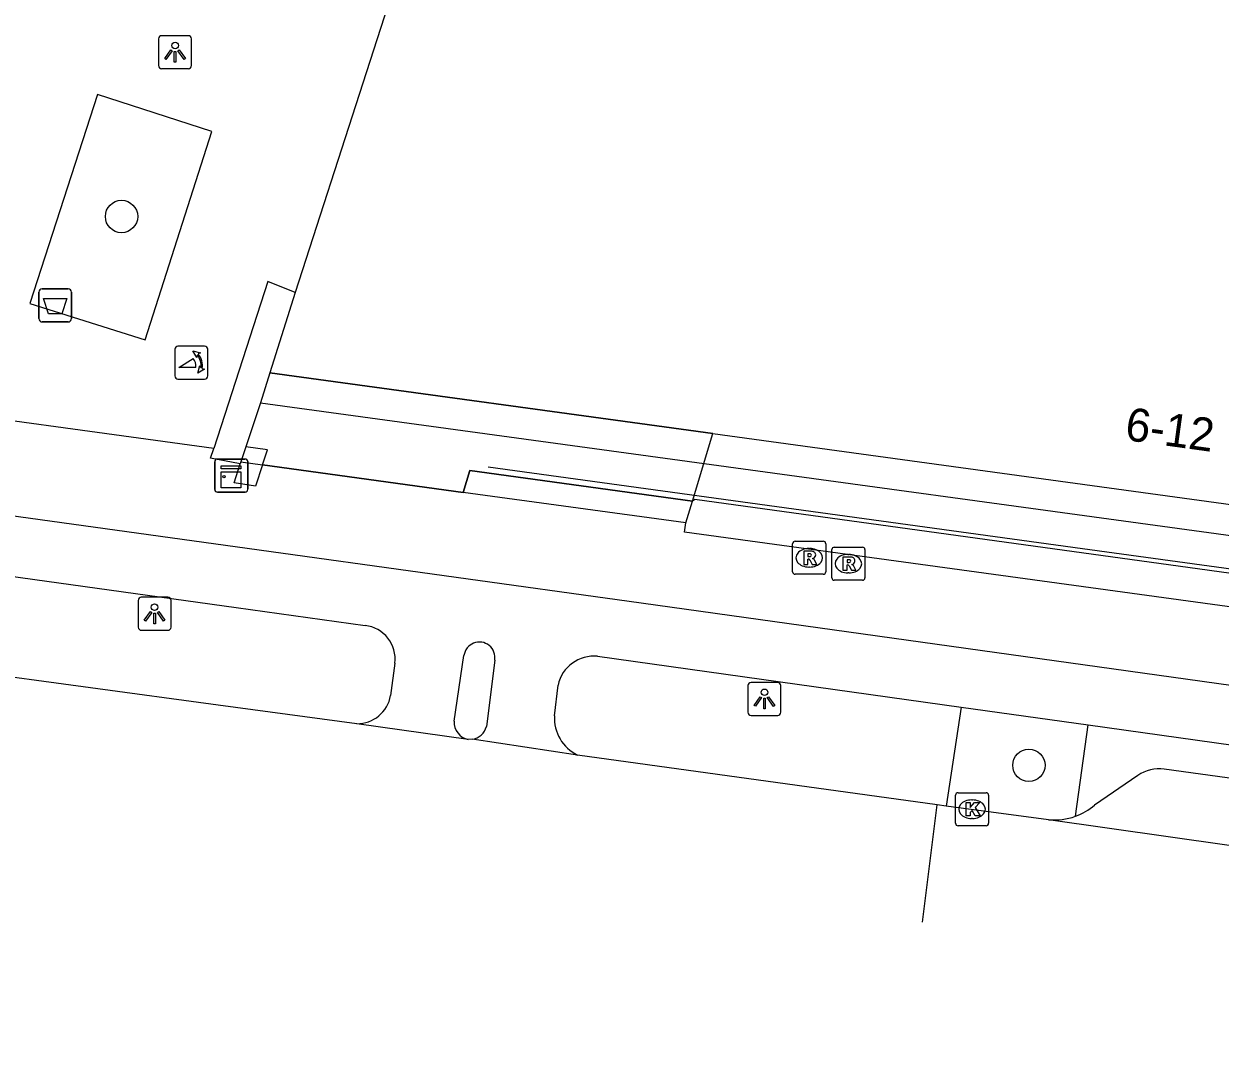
# Model space of a CAD drawing. Extents: x 160676 to 161153, y 383244 to 383713.
# Drawn here: x 160899.21 to 160935.37, y 383255.03 to 383286.17 of the extents above; entities that cross this region are included whole.
import ezdxf

# ---------------------------------------------------------------- set-up
doc = ezdxf.new("R2010")
doc.units = 0
for name, color, linetype in [('IMGEO_Afvalbak', 7, 'Continuous'), ('IMGEO_Berm_open', 7, 'Continuous'), ('IMGEO_Boom', 7, 'Continuous'), ('IMGEO_Fietspad_gesloten', 7, 'Continuous'), ('IMGEO_Kast', 7, 'Continuous'), ('IMGEO_Kolk', 7, 'Continuous'), ('IMGEO_Lichtpunt', 7, 'Continuous'), ('IMGEO_Lijnafwatering', 7, 'Continuous'), ('IMGEO_Pand', 7, 'Continuous'), ('IMGEO_Pand_nummerreeks', 7, 'Continuous'), ('IMGEO_Pand_overbouw', 7, 'Continuous'), ('IMGEO_Parkeervlak_open', 7, 'Continuous'), ('IMGEO_Poller', 7, 'Continuous'), ('IMGEO_Rijbaan_lokaal_gesloten', 7, 'Continuous'), ('IMGEO_Rioolput', 7, 'Continuous'), ('IMGEO_Voetpad_open', 7, 'Continuous')]:
    doc.layers.add(name, color=color, linetype=linetype)

msp = doc.modelspace()

# ---------------------------------------------------------------- linework, layer by layer
at = {"layer": 'IMGEO_Afvalbak'}
for p, q in [((160899.762, 383278.159), (160900.552, 383278.159)), ((160900.552, 383278.159), (160899.762, 383278.159)), ((160899.662, 383277.259), (160899.662, 383278.059)), ((160899.662, 383278.059), (160899.662, 383277.259)), ((160900.652, 383278.059), (160900.652, 383277.259)), ((160900.652, 383277.259), (160900.652, 383278.059)), ((160900.552, 383277.159), (160899.762, 383277.159)), ((160899.762, 383277.159), (160900.552, 383277.159))]:
    msp.add_line(p, q, dxfattribs=at)
msp.add_lwpolyline([(160899.805, 383277.873), (160900.509, 383277.873), (160900.36, 383277.403), (160899.954, 383277.403), (160899.805, 383277.873)], dxfattribs=at)
for centre, start, end in [((160899.762, 383278.059), 90, 180), ((160899.762, 383278.059), 90, 180), ((160900.552, 383278.059), 0, 90), ((160900.552, 383278.059), 360, 90), ((160899.762, 383277.259), 180, 270), ((160899.762, 383277.259), 180, 270), ((160900.552, 383277.259), 270, 0), ((160900.552, 383277.259), 270, 0)]:
    msp.add_arc(centre, 0.1, start, end, dxfattribs=at)
at = {"layer": 'IMGEO_Berm_open'}
for points in [[(160927.544, 383265.517), (160927.098, 383262.525)], [(160931.002, 383262.219), (160931.387, 383264.979)]]:
    msp.add_lwpolyline(points, dxfattribs=at)
at = {"layer": 'IMGEO_Boom'}
for centre in [(160902.164, 383280.346), (160929.593, 383263.759)]:
    msp.add_circle(centre, 0.489, dxfattribs=at)
at = {"layer": 'IMGEO_Fietspad_gesloten'}
for points in [[(160794.456, 383285.635), (160802.2, 383284.6), (160821.26, 383282.051), (160905.957, 383270.323), (160917.876, 383268.672), (161015.584, 383255.032)], [(160879.175, 383272.209), (160905.628, 383268.525), (160909.53, 383267.981)], [(160912.222, 383265.092), (160912.515, 383267.079)], [(160913.448, 383266.937), (160913.196, 383264.937)], [(160916.557, 383267.054), (160927.544, 383265.517)], [(160910.426, 383266.846), (160910.299, 383265.865)], [(160915.249, 383265.258), (160915.362, 383266.182)], [(160927.544, 383265.517), (160931.387, 383264.979)], [(160931.387, 383264.979), (160946.189, 383262.908)]]:
    msp.add_lwpolyline(points, dxfattribs=at)
for centre, radius, start, end in [((160909.423, 383266.976), 1.011, 352.6266, 83.9504), ((160912.982, 383267.013), 0.472, 350.6807, 172.0116), ((160916.446, 383265.952), 1.108, 84.2265, 168.0105), ((160909.282, 383266.048), 1.033, 269.5346, 349.8011), ((160916.495, 383265.191), 1.247, 176.9091, 243.9629), ((160912.736, 383265.049), 0.516, 175.2135, 259.3881), ((160912.689, 383265.063), 0.523, 277.8466, 346.0697)]:
    msp.add_arc(centre, radius, start, end, dxfattribs=at)
at = {"layer": 'IMGEO_Kast'}
for p, q in [((160904.98, 383272.092), (160904.98, 383272.933)), ((160904.98, 383272.933), (160904.98, 383272.092)), ((160905.055, 383273.017), (160905.896, 383273.017)), ((160905.896, 383273.017), (160905.055, 383273.017)), ((160905.98, 383272.942), (160905.98, 383272.101)), ((160905.98, 383272.101), (160905.98, 383272.942)), ((160905.905, 383272.017), (160905.064, 383272.017)), ((160905.064, 383272.017), (160905.905, 383272.017))]:
    msp.add_line(p, q, dxfattribs=at)
for points in [[(160905.175, 383272.807), (160905.775, 383272.807), (160905.775, 383272.722), (160905.175, 383272.722), (160905.175, 383272.807)], [(160905.175, 383272.632), (160905.775, 383272.632), (160905.775, 383272.143), (160905.175, 383272.143), (160905.175, 383272.632)]]:
    msp.add_lwpolyline(points, dxfattribs=at)
msp.add_circle((160905.259, 383272.481), 0.0377, dxfattribs=at)
for centre, start, end in [((160905.058, 383272.939), 92.4484, 184.2845), ((160905.058, 383272.939), 92.4484, 184.2845), ((160905.902, 383272.939), 2.4484, 94.2845), ((160905.902, 383272.939), 2.4484, 94.2845), ((160905.058, 383272.095), 182.4484, 274.2845), ((160905.058, 383272.095), 182.4484, 274.2845), ((160905.902, 383272.095), 272.4484, 4.2845), ((160905.902, 383272.095), 272.4484, 4.2845)]:
    msp.add_arc(centre, 0.0779, start, end, dxfattribs=at)
at = {"layer": 'IMGEO_Kolk'}
for p, q in [((160927.451, 383262.932), (160928.303, 383262.932)), ((160927.376, 383262.006), (160927.376, 383262.858)), ((160927.864, 383262.712), (160927.889, 383262.712)), ((160928.377, 383262.858), (160928.377, 383262.006)), ((160928.303, 383261.932), (160927.451, 383261.932)), ((160927.887, 383262.152), (160927.862, 383262.152))]:
    msp.add_line(p, q, dxfattribs=at)
for points in [[(160927.451, 383262.932), (160928.303, 383262.932)], [(160927.376, 383262.006), (160927.376, 383262.858)], [(160927.697, 383262.632), (160927.82, 383262.632), (160927.82, 383262.481), (160927.95, 383262.632), (160928.114, 383262.632), (160927.968, 383262.481), (160928.121, 383262.232), (160927.969, 383262.232), (160927.884, 383262.396), (160927.82, 383262.329), (160927.82, 383262.232), (160927.697, 383262.232), (160927.697, 383262.632)], [(160928.377, 383262.858), (160928.377, 383262.006)], [(160928.303, 383261.932), (160927.451, 383261.932)]]:
    msp.add_lwpolyline(points, dxfattribs=at)
for centre, start, end in [((160927.453, 383262.856), 91.552, 178.448), ((160927.453, 383262.856), 91.552, 178.448), ((160928.301, 383262.856), 1.552, 88.448), ((160928.301, 383262.856), 1.552, 88.448), ((160927.453, 383262.008), 181.552, 268.448), ((160927.453, 383262.008), 181.552, 268.448), ((160928.301, 383262.008), 271.552, 358.448), ((160928.301, 383262.008), 271.552, 358.448)]:
    msp.add_arc(centre, 0.0765, start, end, dxfattribs=at)
for centre, major_axis, ratio, start_param, end_param in [((160927.863, 383262.432), (-0.387, 0.002), 0.722429, 4.712389, 7.853982), ((160927.888, 383262.432), (-0.39, 0.002), 0.717154, 1.570796, 4.712389)]:
    msp.add_ellipse(centre, major_axis=major_axis, ratio=ratio, start_param=start_param, end_param=end_param, dxfattribs=at)
at = {"layer": 'IMGEO_Lichtpunt'}
for p, q in [((160903.283, 383285.716), (160903.283, 383284.909)), ((160903.283, 383285.716), (160903.283, 383284.909)), ((160904.185, 383285.811), (160903.377, 383285.811)), ((160904.185, 383285.811), (160903.377, 383285.811)), ((160904.279, 383284.909), (160904.279, 383285.716)), ((160904.279, 383284.909), (160904.279, 383285.716)), ((160903.377, 383284.815), (160904.185, 383284.815)), ((160903.377, 383284.815), (160904.185, 383284.815)), ((160902.665, 383268.743), (160902.665, 383267.936)), ((160902.665, 383268.743), (160902.665, 383267.936)), ((160903.567, 383268.838), (160902.759, 383268.838)), ((160903.567, 383268.838), (160902.759, 383268.838)), ((160903.661, 383267.936), (160903.661, 383268.743)), ((160903.661, 383267.936), (160903.661, 383268.743)), ((160902.759, 383267.842), (160903.567, 383267.842)), ((160902.759, 383267.842), (160903.567, 383267.842)), ((160922.002, 383266.263), (160921.194, 383266.263)), ((160922.002, 383266.263), (160921.194, 383266.263)), ((160921.1, 383266.168), (160921.1, 383265.361)), ((160921.1, 383266.168), (160921.1, 383265.361)), ((160922.096, 383265.361), (160922.096, 383266.168)), ((160922.096, 383265.361), (160922.096, 383266.168)), ((160921.194, 383265.267), (160922.002, 383265.267)), ((160921.194, 383265.267), (160922.002, 383265.267))]:
    msp.add_line(p, q, dxfattribs=at)
for points in [[(160903.657, 383285.38), (160903.696, 383285.352), (160903.508, 383285.09), (160903.47, 383285.117), (160903.657, 383285.38)], [(160903.869, 383285.352), (160903.907, 383285.379), (160904.094, 383285.117), (160904.055, 383285.089), (160903.869, 383285.352)], [(160903.759, 383285.332), (160903.806, 383285.332), (160903.806, 383285.01), (160903.759, 383285.01), (160903.759, 383285.332)], [(160903.039, 383268.407), (160903.078, 383268.379), (160902.89, 383268.117), (160902.852, 383268.144), (160903.039, 383268.407)], [(160903.141, 383268.359), (160903.188, 383268.359), (160903.188, 383268.037), (160903.141, 383268.037), (160903.141, 383268.359)], [(160903.251, 383268.379), (160903.289, 383268.406), (160903.476, 383268.144), (160903.437, 383268.116), (160903.251, 383268.379)], [(160921.474, 383265.832), (160921.513, 383265.804), (160921.325, 383265.542), (160921.287, 383265.569), (160921.474, 383265.832)], [(160921.686, 383265.804), (160921.724, 383265.831), (160921.911, 383265.569), (160921.872, 383265.541), (160921.686, 383265.804)], [(160921.576, 383265.784), (160921.623, 383265.784), (160921.623, 383265.462), (160921.576, 383265.462), (160921.576, 383265.784)]]:
    msp.add_lwpolyline(points, dxfattribs=at)
for centre in [(160903.782, 383285.514), (160903.164, 383268.541), (160921.599, 383265.966)]:
    msp.add_circle(centre, 0.0994, dxfattribs=at)
for centre, start, end in [((160903.377, 383285.716), 90, 180), ((160903.377, 383285.716), 90, 180), ((160904.185, 383285.716), 0, 90), ((160904.185, 383285.716), 0, 90), ((160903.377, 383284.909), 180, 270), ((160903.377, 383284.909), 180, 270), ((160904.185, 383284.909), 270, 0), ((160904.185, 383284.909), 270, 360), ((160902.759, 383268.743), 90, 180), ((160902.759, 383268.743), 90, 180), ((160903.567, 383268.743), 0, 90), ((160903.567, 383268.743), 0, 90), ((160902.759, 383267.936), 180, 270), ((160902.759, 383267.936), 180, 270), ((160903.567, 383267.936), 270, 0), ((160903.567, 383267.936), 270, 360), ((160921.194, 383266.168), 90, 180), ((160921.194, 383266.168), 90, 180), ((160922.002, 383266.168), 0, 90), ((160922.002, 383266.168), 0, 90), ((160921.194, 383265.361), 180, 270), ((160921.194, 383265.361), 180, 270), ((160922.002, 383265.361), 270, 0), ((160922.002, 383265.361), 270, 360)]:
    msp.add_arc(centre, 0.0946, start, end, dxfattribs=at)
at = {"layer": 'IMGEO_Lijnafwatering'}
for points in [[(160931.212, 383270.307), (160913.243, 383272.77)], [(160949.181, 383267.844), (160931.212, 383270.307)]]:
    msp.add_lwpolyline(points, dxfattribs=at)
at = {"layer": 'IMGEO_Pand'}
for points in [[(160911.5, 383290.712), (160907.414, 383278.054)], [(160907.414, 383278.054), (160906.652, 383275.617)], [(160906.652, 383275.617), (160920.037, 383273.784), (160958.187, 383268.56), (160960.344, 383268.267)], [(160906.425, 383272.844), (160906.572, 383273.293), (160905.926, 383273.383), (160905.772, 383272.934), (160905.752, 383272.875)], [(160906.425, 383272.844), (160906.213, 383272.197), (160905.572, 383272.294), (160905.752, 383272.875)], [(160919.42, 383271.745), (160912.693, 383272.666), (160912.494, 383272.008)], [(160919.221, 383271.087), (160912.494, 383272.008)], [(160919.221, 383271.087), (160919.42, 383271.745)]]:
    msp.add_lwpolyline(points, dxfattribs=at)
at = {"layer": 'IMGEO_Pand_overbouw'}
msp.add_lwpolyline([(160920.037, 383273.784), (160906.652, 383275.617), (160906.361, 383274.718), (160905.926, 383273.383), (160905.772, 383272.934), (160906.425, 383272.844), (160912.494, 383272.008), (160912.693, 383272.666), (160919.42, 383271.745)], close=True, dxfattribs=at)
at = {"layer": 'IMGEO_Parkeervlak_open'}
for points in [[(160946.008, 383261.707), (160945.542, 383262.006), (160933.685, 383263.646)], [(160932.889, 383263.454), (160931.577, 383262.554)]]:
    msp.add_lwpolyline(points, dxfattribs=at)
for centre, radius, start, end in [((160933.559, 383262.422), 1.231, 84.1317, 122.9904), ((160930.366, 383263.979), 1.871, 264.5955, 289.8629), ((160930.363, 383263.977), 1.87, 289.9775, 310.4734)]:
    msp.add_arc(centre, radius, start, end, dxfattribs=at)
at = {"layer": 'IMGEO_Poller'}
for p, q in [((160903.775, 383276.333), (160903.775, 383275.526)), ((160903.775, 383276.333), (160903.775, 383275.526)), ((160904.677, 383276.428), (160903.869, 383276.428)), ((160904.677, 383276.428), (160903.869, 383276.428)), ((160904.771, 383275.526), (160904.771, 383276.333)), ((160904.771, 383275.526), (160904.771, 383276.333)), ((160903.869, 383275.431), (160904.677, 383275.431)), ((160903.869, 383275.431), (160904.677, 383275.431))]:
    msp.add_line(p, q, dxfattribs=at)
for points in [[(160904.41, 383275.784), (160903.897, 383275.784), (160904.327, 383276.059)], [(160904.454, 383276.157), (160904.442, 383276.084), (160904.317, 383276.289)], [(160904.317, 383276.289), (160904.548, 383276.223), (160904.477, 383276.191)], [(160904.47, 383275.612), (160904.536, 383275.843), (160904.566, 383275.775)], [(160904.602, 383275.748), (160904.674, 383275.737), (160904.47, 383275.612)]]:
    msp.add_lwpolyline(points, dxfattribs=at)
for centre, radius, start, end in [((160903.869, 383276.333), 0.0946, 90, 180), ((160903.869, 383276.333), 0.0946, 90, 180), ((160904.677, 383276.333), 0.0946, 0, 90), ((160904.677, 383276.333), 0.0946, 0, 90), ((160904.082, 383275.834), 0.332, 351.3247, 42.4854), ((160904.096, 383275.844), 0.476, 351.7527, 41.1691), ((160904.096, 383275.844), 0.516, 349.3569, 42.2912), ((160903.869, 383275.526), 0.0946, 180, 270), ((160903.869, 383275.526), 0.0946, 180, 270), ((160904.677, 383275.526), 0.0946, 270, 0), ((160904.677, 383275.526), 0.0946, 270, 0)]:
    msp.add_arc(centre, radius, start, end, dxfattribs=at)
at = {"layer": 'IMGEO_Rijbaan_lokaal_gesloten'}
for points in [[(160909.274, 383265.015), (160905.09, 383265.581), (160897.357, 383266.625)], [(160912.641, 383264.542), (160909.274, 383265.015)], [(160912.76, 383264.545), (160912.641, 383264.542)], [(160915.947, 383264.07), (160912.76, 383264.545)], [(160926.821, 383262.562), (160915.947, 383264.07)], [(160926.374, 383259.023), (160926.821, 383262.562)], [(160927.098, 383262.525), (160926.821, 383262.562)], [(160930.19, 383262.116), (160927.098, 383262.525)], [(160948.208, 383259.553), (160930.19, 383262.116)]]:
    msp.add_lwpolyline(points, dxfattribs=at)
at = {"layer": 'IMGEO_Rioolput'}
for p, q in [((160922.527, 383270.532), (160923.379, 383270.532)), ((160922.452, 383269.606), (160922.452, 383270.458)), ((160922.94, 383270.312), (160922.965, 383270.312)), ((160923.453, 383270.458), (160923.453, 383269.606)), ((160923.637, 383269.427), (160923.637, 383270.279)), ((160923.712, 383270.353), (160924.564, 383270.353)), ((160924.638, 383270.279), (160924.638, 383269.427)), ((160924.125, 383270.133), (160924.15, 383270.133)), ((160923.379, 383269.532), (160922.527, 383269.532)), ((160922.963, 383269.752), (160922.938, 383269.752)), ((160924.148, 383269.573), (160924.123, 383269.573)), ((160924.564, 383269.353), (160923.712, 383269.353))]:
    msp.add_line(p, q, dxfattribs=at)
for points in [[(160922.527, 383270.532), (160923.379, 383270.532)], [(160922.452, 383269.606), (160922.452, 383270.458)], [(160923.041, 383270.23), (160922.789, 383270.232), (160922.789, 383269.832)], [(160923.453, 383270.458), (160923.453, 383269.606)], [(160923.637, 383269.427), (160923.637, 383270.279)], [(160923.712, 383270.353), (160924.564, 383270.353)], [(160924.638, 383270.279), (160924.638, 383269.427)], [(160922.789, 383269.832), (160922.913, 383269.832), (160922.913, 383269.994), (160922.924, 383269.994)], [(160922.967, 383270.151), (160922.913, 383270.151), (160922.913, 383270.07)], [(160922.913, 383270.07), (160922.965, 383270.07)], [(160922.971, 383269.965), (160923.042, 383269.832), (160923.182, 383269.832), (160923.117, 383269.958)], [(160924.226, 383270.051), (160923.974, 383270.053), (160923.974, 383269.653)], [(160923.974, 383269.653), (160924.098, 383269.653), (160924.098, 383269.815), (160924.109, 383269.815)], [(160924.152, 383269.972), (160924.098, 383269.972), (160924.098, 383269.891)], [(160924.098, 383269.891), (160924.15, 383269.891)], [(160923.379, 383269.532), (160922.527, 383269.532)], [(160924.156, 383269.786), (160924.227, 383269.653), (160924.367, 383269.653), (160924.302, 383269.779)], [(160924.564, 383269.353), (160923.712, 383269.353)]]:
    msp.add_lwpolyline(points, dxfattribs=at)
for centre, radius, start, end in [((160922.529, 383270.456), 0.0765, 91.552, 178.448), ((160922.529, 383270.456), 0.0765, 91.552, 178.448), ((160923.377, 383270.456), 0.0765, 1.552, 88.448), ((160923.377, 383270.456), 0.0765, 1.552, 88.448), ((160923.04, 383270.12), 0.109, 350.3612, 89.416), ((160923.714, 383270.277), 0.0765, 91.552, 178.448), ((160923.714, 383270.277), 0.0765, 91.552, 178.448), ((160924.562, 383270.277), 0.0765, 1.552, 88.448), ((160924.562, 383270.277), 0.0765, 1.552, 88.448), ((160922.923, 383269.941), 0.0533, 26.0293, 88.6989), ((160922.949, 383270.259), 0.19, 274.7715, 282.9687), ((160922.973, 383270.055), 0.0964, 77.0061, 93.1865), ((160922.987, 383270.112), 0.0378, 276.6634, 79.6772), ((160923.038, 383270.12), 0.112, 277.5842, 350.9817), ((160923.022, 383269.905), 0.108, 29.5134, 73.7905), ((160924.108, 383269.762), 0.0533, 26.0293, 88.6989), ((160924.134, 383270.08), 0.19, 274.7715, 282.9687), ((160924.158, 383269.876), 0.0964, 77.0061, 93.1865), ((160924.172, 383269.933), 0.0378, 276.6634, 79.6772), ((160924.225, 383269.941), 0.109, 350.3612, 89.416), ((160924.223, 383269.941), 0.112, 277.5842, 350.9817), ((160924.207, 383269.726), 0.108, 29.5134, 73.7905), ((160922.529, 383269.608), 0.0765, 181.552, 268.448), ((160922.529, 383269.608), 0.0765, 181.552, 268.448), ((160923.377, 383269.608), 0.0765, 271.552, 358.448), ((160923.377, 383269.608), 0.0765, 271.552, 358.448), ((160923.714, 383269.429), 0.0765, 181.552, 268.448), ((160923.714, 383269.429), 0.0765, 181.552, 268.448), ((160924.562, 383269.429), 0.0765, 271.552, 358.448), ((160924.562, 383269.429), 0.0765, 271.552, 358.448)]:
    msp.add_arc(centre, radius, start, end, dxfattribs=at)
for centre, major_axis, ratio, start_param, end_param in [((160922.939, 383270.032), (-0.387, 0.002), 0.722429, 4.712389, 7.853982), ((160922.964, 383270.032), (-0.39, 0.002), 0.717154, 1.570796, 4.712389), ((160924.124, 383269.853), (-0.387, 0.002), 0.722429, 4.712389, 7.853982), ((160924.149, 383269.853), (-0.39, 0.002), 0.717154, 1.570796, 4.712389)]:
    msp.add_ellipse(centre, major_axis=major_axis, ratio=ratio, start_param=start_param, end_param=end_param, dxfattribs=at)
at = {"layer": 'IMGEO_Voetpad_open'}
for points in [[(160902.88, 383276.614), (160904.896, 383282.92), (160901.442, 383284.031), (160899.387, 383277.717), (160902.88, 383276.614)], [(160907.414, 383278.054), (160906.582, 383278.383), (160904.953, 383273.337)], [(160906.652, 383275.617), (160906.361, 383274.718), (160987.726, 383263.594)], [(160904.953, 383273.337), (160894.651, 383274.74)], [(160905.752, 383272.875), (160904.857, 383273.04), (160904.953, 383273.337)], [(160912.494, 383272.008), (160906.425, 383272.844)], [(160966.461, 383265.316), (160919.491, 383271.792), (160919.42, 383271.745)], [(160959.423, 383265.299), (160919.184, 383270.806), (160919.221, 383271.087)]]:
    msp.add_lwpolyline(points, dxfattribs=at)

# ---------------------------------------------------------------- texts
at = {"layer": 'IMGEO_Pand_nummerreeks'}
msp.add_text('6-12', height=1, rotation=352.202, dxfattribs=at).set_placement((160932.469, 383273.595))

doc.saveas('drawing.dxf')
